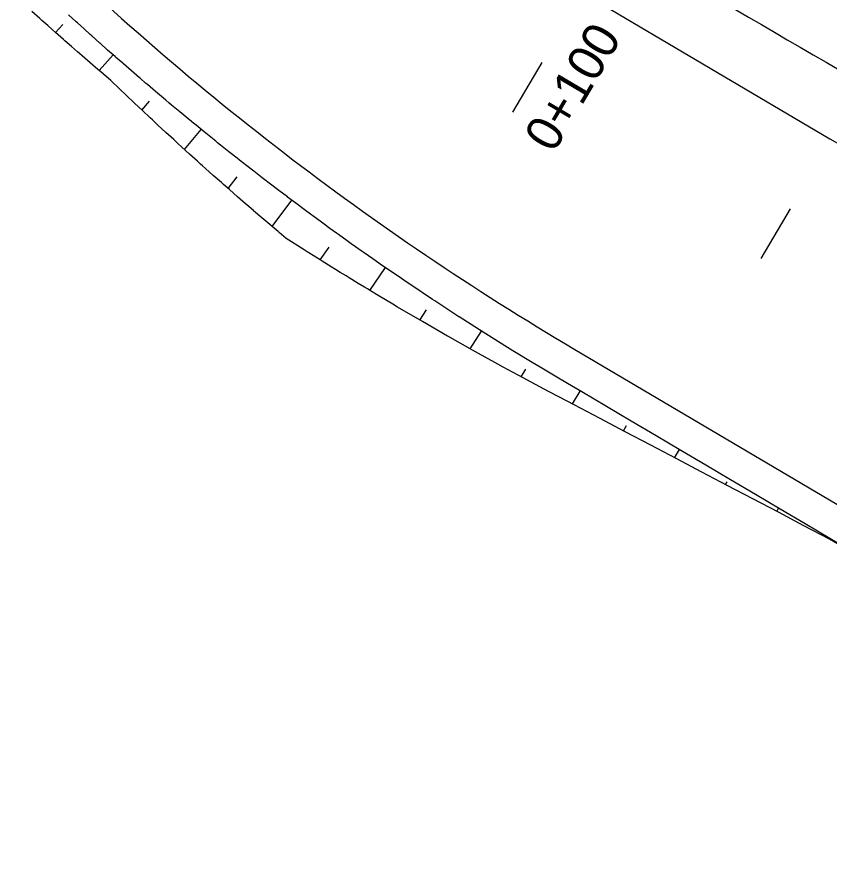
# Model space of a CAD drawing. Extents: x 6503541 to 6503743, y 5888004 to 5888145.
# Drawn here: x 6503697.295 to 6503697.972, y 5888108.649 to 5888109.358 of the extents above; entities that cross this region are included whole.
import ezdxf

# ---------------------------------------------------------------- set-up
doc = ezdxf.new("R2010")
doc.units = 0
doc.layers.add('12', color=7, linetype='Continuous')

msp = doc.modelspace()

# ---------------------------------------------------------------- linework, layer by layer
at = {"layer": '12'}
for p, q in [((6503697.78329, 5888109.42971), (6503697.90427, 5888109.35827)), ((6503697.75642, 5888109.38426), (6503697.97214, 5888109.25688)), ((6503697.75969, 5888109.08131), (6503698.49125, 5888108.64934))]:
    msp.add_line(p, q, dxfattribs=at)
for points in [[(6503697.99241, 5888108.91125), (6503697.97166, 5888108.92331), (6503697.9504, 5888108.93449), (6503697.92913, 5888108.94568), (6503697.90786, 5888108.95686), (6503697.88659, 5888108.96805), (6503697.86533, 5888108.97923), (6503697.84406, 5888108.99042), (6503697.82279, 5888109.0016), (6503697.80153, 5888109.01279), (6503697.78026, 5888109.02397), (6503697.75899, 5888109.03516), (6503697.7468, 5888109.04157), (6503697.73772, 5888109.04634), (6503697.72335, 5888109.05396), (6503697.71651, 5888109.05762), (6503697.70002, 5888109.06654), (6503697.6954, 5888109.06907), (6503697.67683, 5888109.07935), (6503697.6744, 5888109.08071), (6503697.65376, 5888109.09237), (6503697.6535, 5888109.09252), (6503697.63271, 5888109.10451), (6503697.63082, 5888109.10562), (6503697.61203, 5888109.11669), (6503697.60801, 5888109.11908), (6503697.60199, 5888109.12268), (6503697.59439, 5888109.1272), (6503697.5908, 5888109.12936), (6503697.58681, 5888109.13175), (6503697.5843, 5888109.13326), (6503697.57924, 5888109.13632), (6503697.57169, 5888109.14091), (6503697.56906, 5888109.14252), (6503697.56415, 5888109.14553), (6503697.56035, 5888109.14787), (6503697.55663, 5888109.15018), (6503697.54912, 5888109.15484), (6503697.54744, 5888109.15589), (6503697.54163, 5888109.15954), (6503697.53656, 5888109.16273), (6503697.53415, 5888109.16425), (6503697.52669, 5888109.169), (6503697.52595, 5888109.16946), (6503697.51928, 5888109.17383), (6503697.51348, 5888109.1787), (6503697.51245, 5888109.17957), (6503697.50582, 5888109.18517), (6503697.50564, 5888109.18533), (6503697.49884, 5888109.19111), (6503697.49207, 5888109.19691), (6503697.49192, 5888109.19704), (6503697.48634, 5888109.20185), (6503697.48532, 5888109.20274), (6503697.47859, 5888109.20858), (6503697.47188, 5888109.21445), (6503697.47057, 5888109.21559), (6503697.46704, 5888109.2187), (6503697.46519, 5888109.22034), (6503697.45852, 5888109.22625), (6503697.45187, 5888109.23218), (6503697.44944, 5888109.23435), (6503697.4479, 5888109.23573), (6503697.44524, 5888109.23813), (6503697.43863, 5888109.2441), (6503697.43205, 5888109.25009), (6503697.42895, 5888109.25293), (6503697.42851, 5888109.25333), (6503697.42549, 5888109.2561), (6503697.41894, 5888109.26213), (6503697.41242, 5888109.26818), (6503697.41016, 5888109.27029), (6503697.40779, 5888109.2725), (6503697.40592, 5888109.27426), (6503697.39944, 5888109.28035), (6503697.39298, 5888109.28646), (6503697.39155, 5888109.28782), (6503697.38729, 5888109.29189), (6503697.38655, 5888109.2926), (6503697.38013, 5888109.29875), (6503697.37374, 5888109.30492), (6503697.37309, 5888109.30547), (6503697.36702, 5888109.31062), (6503697.36665, 5888109.31094), (6503697.36033, 5888109.31634), (6503697.35384, 5888109.32192), (6503697.35365, 5888109.32208), (6503697.34699, 5888109.32784), (6503697.34547, 5888109.32917), (6503697.34035, 5888109.33363), (6503697.33475, 5888109.33853), (6503697.33373, 5888109.33943), (6503697.32713, 5888109.34525), (6503697.32448, 5888109.34759), (6503697.32055, 5888109.35109), (6503697.31581, 5888109.35532), (6503697.31399, 5888109.35696), (6503697.30744, 5888109.36284)], [(6503697.99267, 5888108.91169), (6503697.97201, 5888108.92389), (6503697.95134, 5888108.93609), (6503697.93067, 5888108.9483), (6503697.91001, 5888108.9605), (6503697.88934, 5888108.9727), (6503697.86868, 5888108.98491), (6503697.84801, 5888108.99711), (6503697.82734, 5888109.00931), (6503697.80668, 5888109.02151), (6503697.78601, 5888109.03372), (6503697.76535, 5888109.04592), (6503697.75349, 5888109.05292), (6503697.74468, 5888109.05812), (6503697.73072, 5888109.06644), (6503697.72408, 5888109.07044), (6503697.70809, 5888109.0802), (6503697.7036, 5888109.08296), (6503697.6856, 5888109.09421), (6503697.68325, 5888109.09569), (6503697.66326, 5888109.10847), (6503697.66301, 5888109.10863), (6503697.6429, 5888109.12177), (6503697.64108, 5888109.12298), (6503697.62292, 5888109.13512), (6503697.61904, 5888109.13775), (6503697.61322, 5888109.1417), (6503697.60595, 5888109.14668), (6503697.60251, 5888109.14905), (6503697.5987, 5888109.15168), (6503697.5963, 5888109.15334), (6503697.59147, 5888109.1567), (6503697.58426, 5888109.16176), (6503697.58174, 5888109.16353), (6503697.57706, 5888109.16683), (6503697.57344, 5888109.16941), (6503697.56989, 5888109.17194), (6503697.56273, 5888109.17707), (6503697.56113, 5888109.17822), (6503697.5556, 5888109.18222), (6503697.55078, 5888109.18573), (6503697.54848, 5888109.1874), (6503697.54138, 5888109.19261), (6503697.54068, 5888109.19313), (6503697.5343, 5888109.19784), (6503697.5283, 5888109.2023), (6503697.52724, 5888109.2031), (6503697.52039, 5888109.20824), (6503697.5202, 5888109.20838), (6503697.51318, 5888109.21369), (6503697.50618, 5888109.21902), (6503697.50603, 5888109.21914), (6503697.50026, 5888109.22356), (6503697.4992, 5888109.22438), (6503697.49224, 5888109.22976), (6503697.4853, 5888109.23516), (6503697.48396, 5888109.23622), (6503697.4803, 5888109.23909), (6503697.47839, 5888109.2406), (6503697.47149, 5888109.24605), (6503697.46461, 5888109.25153), (6503697.46209, 5888109.25355), (6503697.46051, 5888109.25482), (6503697.45775, 5888109.25704), (6503697.45091, 5888109.26256), (6503697.4441, 5888109.26812), (6503697.44088, 5888109.27075), (6503697.44043, 5888109.27112), (6503697.4373, 5888109.2737), (6503697.43053, 5888109.2793), (6503697.42377, 5888109.28492), (6503697.42143, 5888109.28688), (6503697.41898, 5888109.28894), (6503697.41704, 5888109.29057), (6503697.41033, 5888109.29624), (6503697.40364, 5888109.30194), (6503697.40216, 5888109.30321), (6503697.39774, 5888109.307), (6503697.39697, 5888109.30766), (6503697.39032, 5888109.3134), (6503697.3837, 5888109.31917), (6503697.38306, 5888109.31973), (6503697.3771, 5888109.32496), (6503697.37672, 5888109.32529), (6503697.37051, 5888109.33078), (6503697.36414, 5888109.33645), (6503697.36395, 5888109.33661), (6503697.35742, 5888109.34247), (6503697.35592, 5888109.34382), (6503697.3509, 5888109.34836), (6503697.3454, 5888109.35335), (6503697.34441, 5888109.35426), (6503697.33793, 5888109.36019)], [(6503697.32703, 5888109.34534), (6503697.33323, 5888109.35209)], [(6503697.36353, 5888109.31361), (6503697.37511, 5888109.32673)], [(6503697.70793, 5888109.2791), (6503697.73234, 5888109.32044)], [(6503697.39904, 5888109.28073), (6503697.40523, 5888109.28804)], [(6503697.43458, 5888109.24778), (6503697.44835, 5888109.26468)], [(6503697.47076, 5888109.21543), (6503697.47831, 5888109.22508)], [(6503697.50758, 5888109.18369), (6503697.52398, 5888109.20556)], [(6503697.939, 5888109.19841), (6503697.91459, 5888109.15707)], [(6503697.54739, 5888109.15593), (6503697.55503, 5888109.16654)], [(6503697.58881, 5888109.13055), (6503697.60189, 5888109.14949)], [(6503697.63053, 5888109.10579), (6503697.63609, 5888109.1142)], [(6503697.67258, 5888109.08173), (6503697.68195, 5888109.09653)], [(6503697.71498, 5888109.05845), (6503697.71887, 5888109.06485)], [(6503697.7576, 5888109.03589), (6503697.76401, 5888109.04671)], [(6503697.80015, 5888109.01351), (6503697.80274, 5888109.01791)], [(6503697.84268, 5888108.99114), (6503697.84667, 5888108.9979)], [(6503697.88522, 5888108.96877), (6503697.88661, 5888108.97113)], [(6503697.92775, 5888108.9464), (6503697.92934, 5888108.94909)], [(6503697.96826, 5888108.9251), (6503697.9687, 5888108.92585)]]:
    msp.add_lwpolyline(points, dxfattribs=at)
for centre, radius, start, end in [((6503698.97999, 5888111.14792), 2.4, 225.40646, 239.43893), ((6503700.95501, 5888114.5248), 5.904, 239.438926, 243.253001), ((6503700.95501, 5888114.5248), 5.952, 239.438926, 243.253001), ((6503700.95501, 5888114.5248), 6, 239.438926, 243.253001), ((6503701.02288, 5888114.42341), 6, 239.438926, 243.253001)]:
    msp.add_arc(centre, radius, start, end, dxfattribs=at)

# ---------------------------------------------------------------- texts
msp.add_text('0+100', height=0.03, rotation=59.43893, dxfattribs=at).set_placement((6503697.74186, 5888109.24408))

doc.saveas('drawing.dxf')
